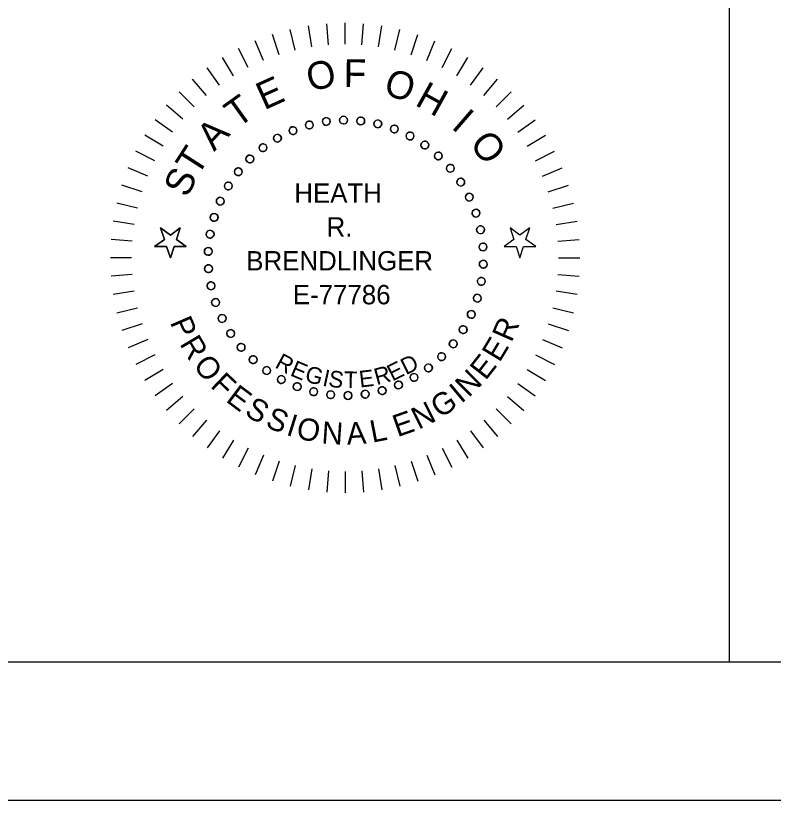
# Model space of a CAD drawing. Extents: x -5.9 to 34, y 0 to 22.
# Drawn here: x 23.816 to 26.559, y 0 to 2.839 of the extents above; entities that cross this region are included whole.
import ezdxf

# ---------------------------------------------------------------- set-up
doc = ezdxf.new("R2010")
doc.units = 0
for name, color, linetype in [('Default', 7, 'Continuous'), ('SH_Border', 7, 'Continuous'), ('SH_Cut_Line', 7, 'Continuous'), ('SH_Data', 7, 'Continuous')]:
    doc.layers.add(name, color=color, linetype=linetype)

msp = doc.modelspace()

# ---------------------------------------------------------------- linework, layer by layer
at = {"layer": 'Default'}
for points in [[(25.009, 2.7357), (25.009, 2.8128)], [(24.8286, 2.7144), (24.8106, 2.7893)], [(24.8881, 2.7262), (24.8761, 2.8023)], [(24.9484, 2.7334), (24.9423, 2.8102)], [(25.0697, 2.7334), (25.0757, 2.8102)], [(25.1299, 2.7262), (25.142, 2.8023)], [(25.1895, 2.7144), (25.2075, 2.7893)], [(24.7702, 2.6979), (24.7464, 2.7712)], [(25.2479, 2.6979), (25.2717, 2.7712)], [(24.7132, 2.6769), (24.6837, 2.7481)], [(25.3048, 2.6769), (25.3343, 2.7481)], [(24.6581, 2.6515), (24.6231, 2.7202)], [(25.3599, 2.6515), (25.3949, 2.7202)], [(24.6052, 2.6218), (24.5649, 2.6876)], [(25.4129, 2.6218), (25.4532, 2.6876)], [(24.5547, 2.5881), (24.5094, 2.6505)], [(25.4634, 2.5881), (25.5087, 2.6505)], [(24.507, 2.5505), (24.457, 2.6092)], [(25.511, 2.5505), (25.5611, 2.6092)], [(24.4625, 2.5094), (24.408, 2.5638)], [(25.5556, 2.5094), (25.6101, 2.5638)], [(24.4213, 2.4648), (24.3627, 2.5148)], [(25.5968, 2.4648), (25.6554, 2.5148)], [(24.3837, 2.4171), (24.3213, 2.4624)], [(25.6344, 2.4171), (25.6967, 2.4624)], [(24.35, 2.3667), (24.2843, 2.4069)], [(25.6681, 2.3667), (25.7338, 2.4069)], [(24.3203, 2.3137), (24.2517, 2.3487)], [(25.6977, 2.3137), (25.7664, 2.3487)], [(24.2949, 2.2586), (24.2237, 2.2881)], [(25.7231, 2.2586), (25.7943, 2.2881)], [(24.2739, 2.2016), (24.2006, 2.2255)], [(25.7442, 2.2016), (25.8174, 2.2255)], [(24.2574, 2.1432), (24.1825, 2.1612)], [(25.7606, 2.1432), (25.8356, 2.1612)], [(24.2456, 2.0837), (24.1695, 2.0958)], [(25.7725, 2.0837), (25.8486, 2.0958)], [(24.3545, 2.0295), (24.3192, 2.0039), (24.3628, 2.0039), (24.3762, 1.9624), (24.3897, 2.0039), (24.4333, 2.0039), (24.398, 2.0295), (24.4115, 2.071), (24.3762, 2.0454), (24.341, 2.071), (24.3545, 2.0295)], [(25.6771, 2.071), (25.6418, 2.0454), (25.6065, 2.071), (25.62, 2.0295), (25.5847, 2.0039), (25.6283, 2.0039), (25.6418, 1.9624), (25.6553, 2.0039), (25.6989, 2.0039), (25.6636, 2.0295), (25.6771, 2.071)], [(24.2385, 2.0234), (24.1616, 2.0295)], [(25.7796, 2.0234), (25.8564, 2.0295)], [(24.2361, 1.9628), (24.159, 1.9628)], [(25.782, 1.9628), (25.8591, 1.9628)], [(24.2385, 1.9021), (24.1616, 1.8961)], [(25.7796, 1.9021), (25.8564, 1.8961)], [(24.2456, 1.8419), (24.1695, 1.8298)], [(25.8486, 1.8298), (25.7725, 1.8419)], [(24.1825, 1.7644), (24.2574, 1.7823)], [(25.7606, 1.7823), (25.8356, 1.7644)], [(24.2739, 1.7239), (24.2006, 1.7001)], [(25.7442, 1.7239), (25.8174, 1.7001)], [(24.2949, 1.667), (24.2237, 1.6375)], [(25.7231, 1.667), (25.7943, 1.6375)], [(24.3203, 1.6119), (24.2517, 1.5769)], [(25.6977, 1.6119), (25.7664, 1.5769)], [(24.35, 1.5589), (24.2843, 1.5187)], [(25.6681, 1.5589), (25.7338, 1.5187)], [(24.3837, 1.5085), (24.3213, 1.4632)], [(25.6344, 1.5085), (25.6967, 1.4632)], [(24.4213, 1.4608), (24.3627, 1.4107)], [(25.5968, 1.4608), (25.6554, 1.4107)], [(24.4625, 1.4162), (24.408, 1.3617)], [(25.5556, 1.4162), (25.6101, 1.3617)], [(24.507, 1.375), (24.457, 1.3164)], [(25.511, 1.375), (25.5611, 1.3164)], [(24.5547, 1.3375), (24.5094, 1.2751)], [(25.4634, 1.3375), (25.5087, 1.2751)], [(24.6052, 1.3037), (24.5649, 1.238)], [(25.4129, 1.3037), (25.4532, 1.238)], [(24.6581, 1.2741), (24.6231, 1.2054)], [(25.3599, 1.2741), (25.3949, 1.2054)], [(24.7132, 1.2487), (24.6837, 1.1775)], [(24.7702, 1.2277), (24.7464, 1.1544)], [(25.2479, 1.2277), (25.2717, 1.1544)], [(25.3048, 1.2487), (25.3343, 1.1775)], [(24.8286, 1.2112), (24.8106, 1.1363)], [(24.8881, 1.1993), (24.8761, 1.1232)], [(25.1299, 1.1993), (25.142, 1.1232)], [(25.1895, 1.2112), (25.2075, 1.1363)], [(24.9484, 1.1922), (24.9423, 1.1154)], [(25.009, 1.1898), (25.009, 1.1128)], [(25.0697, 1.1922), (25.0757, 1.1154)]]:
    msp.add_lwpolyline(points, dxfattribs=at)
for points in [[(24.341, 2.071), (24.3762, 2.0454), (24.4115, 2.071), (24.398, 2.0295), (24.4333, 2.0039), (24.3897, 2.0039), (24.3762, 1.9624), (24.3628, 2.0039), (24.3192, 2.0039), (24.3545, 2.0295)], [(25.6771, 2.071), (25.6418, 2.0454), (25.6065, 2.071), (25.62, 2.0295), (25.5847, 2.0039), (25.6283, 2.0039), (25.6418, 1.9624), (25.6553, 2.0039), (25.6989, 2.0039), (25.6636, 2.0295)]]:
    msp.add_lwpolyline(points, close=True, dxfattribs=at)
for centre in [(24.9407, 2.4564), (25.0031, 2.4613), (25.0656, 2.4584), (24.8794, 2.4437), (25.1273, 2.4477), (25.1871, 2.4293), (24.8202, 2.4234), (25.2441, 2.4036), (24.764, 2.3958), (25.2975, 2.3709), (24.7118, 2.3614), (24.6642, 2.3207), (25.3464, 2.3318), (25.39, 2.2869), (24.6221, 2.2744), (25.4276, 2.2369), (24.5861, 2.2232), (25.4586, 2.1826), (24.5569, 2.1679), (25.4826, 2.1247), (24.5348, 2.1093), (25.4991, 2.0644), (24.5202, 2.0485), (25.508, 2.0024), (24.5134, 1.9863), (24.5144, 1.9237), (25.509, 1.9399), (24.5233, 1.8617), (25.5022, 1.8777), (25.4876, 1.8168), (24.5398, 1.8014), (25.4655, 1.7582), (24.5638, 1.7436), (25.4362, 1.7029), (24.5948, 1.6892), (24.6324, 1.6392), (25.4003, 1.6517), (25.3582, 1.6054), (24.676, 1.5943), (24.7249, 1.5552), (25.3106, 1.5647), (24.7783, 1.5225), (25.2583, 1.5303), (24.8353, 1.4968), (25.2022, 1.5028), (24.8951, 1.4784), (24.9568, 1.4677), (25.0193, 1.4648), (25.0817, 1.4697), (25.143, 1.4825)]:
    msp.add_circle(centre, 0.0141, dxfattribs=at)
for centre, radius, start, end in [((24.9407, 2.4564), 0.0141, 7.2, 187.2), ((25.0031, 2.4613), 0.0141, 0, 180), ((25.0656, 2.4584), 0.0141, 352.8, 172.8), ((24.8794, 2.4437), 0.0141, 14.4, 194.4), ((24.8794, 2.4437), 0.0141, 292.5271, 14.4), ((24.9407, 2.4564), 0.0141, 187.2, 270.9371), ((25.0112, 1.9631), 0.4843, 97.9226, 98.3416), ((24.9407, 2.4564), 0.0141, 285.3271, 7.2), ((25.0031, 2.4613), 0.0141, 180, 263.7371), ((25.0112, 1.9631), 0.4843, 90.7226, 91.1416), ((25.0031, 2.4613), 0.0141, 278.1271, 360), ((25.0656, 2.4584), 0.0141, 172.8, 256.5371), ((25.0112, 1.9631), 0.4843, 83.5226, 83.9416), ((25.0656, 2.4584), 0.0141, 270.9271, 352.8), ((25.1273, 2.4477), 0.0141, 165.6, 249.3371), ((25.1273, 2.4477), 0.0141, 345.6, 165.6), ((25.1273, 2.4477), 0.0141, 263.7271, 345.6), ((25.1871, 2.4293), 0.0141, 338.4, 158.4), ((24.8202, 2.4234), 0.0141, 21.6, 201.6), ((24.8202, 2.4234), 0.0141, 201.6, 285.3371), ((24.8202, 2.4234), 0.0141, 299.7271, 21.6), ((24.8794, 2.4437), 0.0141, 194.4, 278.1371), ((25.0112, 1.9631), 0.4843, 105.1226, 105.5416), ((25.0112, 1.9631), 0.4843, 76.3226, 76.7416), ((25.1871, 2.4293), 0.0141, 158.4, 242.1371), ((25.0112, 1.9631), 0.4843, 69.1226, 69.5416), ((25.1871, 2.4293), 0.0141, 256.5271, 338.4), ((25.2441, 2.4036), 0.0141, 331.2, 151.2), ((24.764, 2.3958), 0.0141, 28.8, 208.8), ((24.764, 2.3958), 0.0141, 208.8, 292.5371), ((24.764, 2.3958), 0.0141, 306.9271, 28.8), ((25.0112, 1.9631), 0.4843, 112.3226, 112.7416), ((25.2441, 2.4036), 0.0141, 151.2, 234.9371), ((25.0112, 1.9631), 0.4843, 61.9226, 62.3416), ((25.2441, 2.4036), 0.0141, 249.3271, 331.2), ((25.2975, 2.3709), 0.0141, 324, 144), ((24.7118, 2.3614), 0.0141, 36, 216), ((24.7118, 2.3614), 0.0141, 314.1271, 36), ((25.0112, 1.9631), 0.4843, 119.5226, 119.9416), ((25.2975, 2.3709), 0.0141, 144, 227.7371), ((25.0112, 1.9631), 0.4843, 54.7226, 55.1416), ((25.2975, 2.3709), 0.0141, 242.1271, 324), ((24.6642, 2.3207), 0.0141, 43.2, 223.2), ((24.6642, 2.3207), 0.0141, 321.3271, 43.2), ((24.7118, 2.3614), 0.0141, 216, 299.7371), ((25.0112, 1.9631), 0.4843, 126.7226, 127.1416), ((25.3464, 2.3318), 0.0141, 136.8, 220.5371), ((25.3464, 2.3318), 0.0141, 316.8, 136.8), ((24.6642, 2.3207), 0.0141, 223.2, 306.9371), ((25.0112, 1.9631), 0.4843, 133.9226, 134.3416), ((25.0112, 1.9631), 0.4843, 47.5226, 47.9416), ((25.3464, 2.3318), 0.0141, 234.9271, 316.8), ((25.39, 2.2869), 0.0141, 309.6, 129.6), ((24.6221, 2.2744), 0.0141, 50.4, 230.4), ((24.6221, 2.2744), 0.0141, 328.5271, 50.4), ((25.39, 2.2869), 0.0141, 129.6, 213.3371), ((25.0112, 1.9631), 0.4843, 40.3226, 40.7416), ((25.39, 2.2869), 0.0141, 227.7271, 309.6), ((24.6221, 2.2744), 0.0141, 230.4, 314.1371), ((25.0112, 1.9631), 0.4843, 141.1226, 141.5416), ((25.4276, 2.2369), 0.0141, 122.4, 206.1371), ((25.4276, 2.2369), 0.0141, 302.4, 122.4), ((24.5861, 2.2232), 0.0141, 57.6, 237.6), ((24.5861, 2.2232), 0.0141, 335.7271, 57.6), ((25.0112, 1.9631), 0.4843, 148.3226, 148.7416), ((25.0112, 1.9631), 0.4843, 33.1226, 33.5416), ((25.4276, 2.2369), 0.0141, 220.5271, 302.4), ((24.5861, 2.2232), 0.0141, 237.6, 321.3371), ((25.4586, 2.1826), 0.0141, 115.2, 198.9371), ((25.4586, 2.1826), 0.0141, 295.2, 115.2), ((24.5569, 2.1679), 0.0141, 64.8, 244.8), ((24.5569, 2.1679), 0.0141, 244.8, 328.5371), ((24.5569, 2.1679), 0.0141, 342.9271, 64.8), ((25.0112, 1.9631), 0.4843, 155.5226, 155.9416), ((25.0112, 1.9631), 0.4843, 25.9226, 26.3416), ((25.4586, 2.1826), 0.0141, 213.3271, 295.2), ((25.4826, 2.1247), 0.0141, 108, 191.7371), ((25.4826, 2.1247), 0.0141, 288, 108), ((24.5348, 2.1093), 0.0141, 72, 252), ((24.5348, 2.1093), 0.0141, 252, 335.7371), ((24.5348, 2.1093), 0.0141, 350.1271, 72), ((25.0112, 1.9631), 0.4843, 162.7226, 163.1416), ((25.0112, 1.9631), 0.4843, 18.7226, 19.1416), ((25.4826, 2.1247), 0.0141, 206.1271, 288), ((25.4991, 2.0644), 0.0141, 100.8, 184.5371), ((25.4991, 2.0644), 0.0141, 280.8, 100.8), ((24.5202, 2.0485), 0.0141, 79.2, 259.2), ((24.5202, 2.0485), 0.0141, 259.2, 342.9371), ((24.5202, 2.0485), 0.0141, 357.3271, 79.2), ((25.0112, 1.9631), 0.4843, 169.9226, 170.3416), ((25.0112, 1.9631), 0.4843, 11.5226, 11.9416), ((25.4991, 2.0644), 0.0141, 198.9271, 280.8), ((25.508, 2.0024), 0.0141, 93.6, 177.3371), ((25.508, 2.0024), 0.0141, 273.6, 93.6), ((24.5134, 1.9863), 0.0141, 86.4, 266.4), ((24.5134, 1.9863), 0.0141, 4.5271, 86.4), ((25.0112, 1.9631), 0.4843, 4.3226, 4.7416), ((25.508, 2.0024), 0.0141, 191.7271, 273.6), ((24.5134, 1.9863), 0.0141, 266.4, 350.1371), ((25.0112, 1.9631), 0.4843, 177.1226, 177.5416), ((24.5144, 1.9237), 0.0141, 93.6, 273.6), ((24.5144, 1.9237), 0.0141, 11.7271, 93.6), ((25.0112, 1.9631), 0.4843, 357.1226, 357.5416), ((25.509, 1.9399), 0.0141, 184.5271, 266.4), ((25.509, 1.9399), 0.0141, 86.4, 170.1371), ((25.509, 1.9399), 0.0141, 266.4, 86.4), ((24.5144, 1.9237), 0.0141, 273.6, 357.3371), ((25.0112, 1.9631), 0.4843, 184.3226, 184.7416), ((24.5233, 1.8617), 0.0141, 100.8, 280.8), ((24.5233, 1.8617), 0.0141, 18.9271, 100.8), ((25.0112, 1.9631), 0.4843, 349.9226, 350.3416), ((25.5022, 1.8777), 0.0141, 177.3271, 259.2), ((25.5022, 1.8777), 0.0141, 79.2, 162.9371), ((25.5022, 1.8777), 0.0141, 259.2, 79.2), ((24.5233, 1.8617), 0.0141, 280.8, 4.5371), ((25.0112, 1.9631), 0.4843, 191.5226, 191.9416), ((25.4876, 1.8168), 0.0141, 170.1271, 252), ((25.0112, 1.9631), 0.4843, 342.7226, 343.1416), ((25.4876, 1.8168), 0.0141, 72, 155.7371), ((25.4876, 1.8168), 0.0141, 252, 72), ((24.5398, 1.8014), 0.0141, 108, 288), ((24.5398, 1.8014), 0.0141, 26.1271, 108), ((24.5398, 1.8014), 0.0141, 288, 11.7371), ((25.0112, 1.9631), 0.4843, 198.7226, 199.1416), ((25.4655, 1.7582), 0.0141, 162.9271, 244.8), ((25.0112, 1.9631), 0.4843, 335.5226, 335.9416), ((25.4655, 1.7582), 0.0141, 64.8, 148.5371), ((25.4655, 1.7582), 0.0141, 244.8, 64.8), ((24.5638, 1.7436), 0.0141, 115.2, 295.2), ((24.5638, 1.7436), 0.0141, 33.3271, 115.2), ((24.5638, 1.7436), 0.0141, 295.2, 18.9371), ((25.0112, 1.9631), 0.4843, 205.9226, 206.3416), ((25.4362, 1.7029), 0.0141, 155.7271, 237.6), ((25.0112, 1.9631), 0.4843, 328.3226, 328.7416), ((25.4362, 1.7029), 0.0141, 57.6, 141.3371), ((25.4362, 1.7029), 0.0141, 237.6, 57.6), ((24.5948, 1.6892), 0.0141, 122.4, 302.4), ((24.5948, 1.6892), 0.0141, 40.5271, 122.4), ((24.5948, 1.6892), 0.0141, 302.4, 26.1371), ((25.0112, 1.9631), 0.4843, 213.1226, 213.5416), ((24.6324, 1.6392), 0.0141, 129.6, 309.6), ((24.6324, 1.6392), 0.0141, 47.7271, 129.6), ((24.6324, 1.6392), 0.0141, 309.6, 33.3371), ((25.0112, 1.9631), 0.4843, 220.3226, 220.7416), ((25.4003, 1.6517), 0.0141, 148.5271, 230.4), ((25.0112, 1.9631), 0.4843, 321.1226, 321.5416), ((25.4003, 1.6517), 0.0141, 50.4, 134.1371), ((25.4003, 1.6517), 0.0141, 230.4, 50.4), ((25.3582, 1.6054), 0.0141, 43.2, 126.9371), ((24.676, 1.5943), 0.0141, 136.8, 316.8), ((24.676, 1.5943), 0.0141, 54.9271, 136.8), ((25.0112, 1.9631), 0.4843, 227.5226, 227.9416), ((24.676, 1.5943), 0.0141, 316.8, 40.5371), ((25.3582, 1.6054), 0.0141, 141.3271, 223.2), ((25.0112, 1.9631), 0.4843, 313.9226, 314.3416), ((25.3582, 1.6054), 0.0141, 223.2, 43.2), ((24.7249, 1.5552), 0.0141, 144, 324), ((24.7249, 1.5552), 0.0141, 62.1271, 144), ((25.0112, 1.9631), 0.4843, 234.7226, 235.1416), ((24.7249, 1.5552), 0.0141, 324, 47.7371), ((25.3106, 1.5647), 0.0141, 134.1271, 216), ((25.3106, 1.5647), 0.0141, 216, 36), ((25.0112, 1.9631), 0.4843, 306.7226, 307.1416), ((25.3106, 1.5647), 0.0141, 36, 119.7371), ((24.7783, 1.5225), 0.0141, 69.3271, 151.2), ((25.0112, 1.9631), 0.4843, 241.9226, 242.3416), ((24.7783, 1.5225), 0.0141, 331.2, 54.9371), ((25.2583, 1.5303), 0.0141, 126.9271, 208.8), ((25.2583, 1.5303), 0.0141, 208.8, 28.8), ((25.0112, 1.9631), 0.4843, 299.5226, 299.9416), ((25.2583, 1.5303), 0.0141, 28.8, 112.5371), ((24.7783, 1.5225), 0.0141, 151.2, 331.2), ((24.8353, 1.4968), 0.0141, 76.5271, 158.4), ((25.0112, 1.9631), 0.4843, 249.1226, 249.5416), ((24.8353, 1.4968), 0.0141, 338.4, 62.1371), ((25.2022, 1.5028), 0.0141, 119.7271, 201.6), ((25.2022, 1.5028), 0.0141, 201.6, 21.6), ((25.0112, 1.9631), 0.4843, 292.3226, 292.7416), ((25.2022, 1.5028), 0.0141, 21.6, 105.3371), ((24.8353, 1.4968), 0.0141, 158.4, 338.4), ((24.8951, 1.4784), 0.0141, 165.6, 345.6), ((24.8951, 1.4784), 0.0141, 83.7271, 165.6), ((25.0112, 1.9631), 0.4843, 256.3226, 256.7416), ((24.8951, 1.4784), 0.0141, 345.6, 69.3371), ((24.9568, 1.4677), 0.0141, 90.9271, 172.8), ((25.0112, 1.9631), 0.4843, 263.5226, 263.9416), ((24.9568, 1.4677), 0.0141, 352.8, 76.5371), ((25.0193, 1.4648), 0.0141, 98.1271, 180), ((25.0112, 1.9631), 0.4843, 270.7226, 271.1416), ((25.0193, 1.4648), 0.0141, 360, 83.7371), ((25.0817, 1.4697), 0.0141, 105.3271, 187.2), ((25.0112, 1.9631), 0.4843, 277.9226, 278.3416), ((25.0817, 1.4697), 0.0141, 7.2, 90.9371), ((25.143, 1.4825), 0.0141, 112.5271, 194.4), ((25.143, 1.4825), 0.0141, 194.4, 14.4), ((25.0112, 1.9631), 0.4843, 285.1226, 285.5416), ((25.143, 1.4825), 0.0141, 14.4, 98.1371), ((24.9568, 1.4677), 0.0141, 172.8, 352.8), ((25.0193, 1.4648), 0.0141, 180, 0), ((25.0817, 1.4697), 0.0141, 187.2, 7.2)]:
    msp.add_arc(centre, radius, start, end, dxfattribs=at)
at = {"layer": 'SH_Border'}
msp.add_lwpolyline([(1.5, 21.5), (33.5, 21.5), (33.5, 0.5), (1.5, 0.5)], close=True, dxfattribs=at)
at = {"layer": 'SH_Cut_Line'}
msp.add_lwpolyline([(0, 0), (34, 0), (34, 22), (0, 22)], close=True, dxfattribs=at)
at = {"layer": 'SH_Data'}
msp.add_line((26.4, 0.5), (26.4, 3.75), dxfattribs=at)

# ---------------------------------------------------------------- texts
at = {"layer": 'Default'}
for s, height, rotation, p in [('O', 0.1, 13.3854, (24.8823, 2.5639)), ('F', 0.1, 359.678, (25.0037, 2.5812)), ('O', 0.1, 342.0191, (25.1437, 2.5563)), ('E', 0.1, 24.2623, (24.716, 2.4964)), ('H', 0.1, 330.9889, (25.2583, 2.5174)), ('T', 0.1, 35.6514, (24.6195, 2.4305)), ('I', 0.1, 319.1518, (25.3904, 2.434)), ('A', 0.1, 46.5856, (24.535, 2.3455)), ('O', 0.1, 307.5099, (25.4565, 2.3748)), ('T', 0.1, 57.2766, (24.4742, 2.2543)), ('S', 0.1, 64.8956, (24.4385, 2.1774)), ('P', 0.08, 293.3065, (24.374, 1.7298)), ('R', 0.08, 66.294, (25.6112, 1.6543)), ('R', 0.08, 300.7913, (24.4082, 1.6517)), ('E', 0.08, 58.867, (25.5679, 1.5817)), ('O', 0.08, 308.9294, (24.4563, 1.5722)), ('R', 0.06, 331.5179, (24.7514, 1.5678)), ('E', 0.06, 337.0101, (24.8066, 1.5385)), ('E', 0.06, 26.5869, (25.18, 1.515)), ('D', 0.06, 26.8755, (25.2294, 1.5379)), ('E', 0.08, 51.8972, (25.5175, 1.5167)), ('G', 0.06, 344.9102, (24.8599, 1.5166)), ('R', 0.06, 15.2924, (25.1232, 1.5018)), ('F', 0.08, 316.3676, (24.5183, 1.4975)), ('I', 0.06, 347.8825, (24.9242, 1.501)), ('S', 0.06, 351.4682, (24.9458, 1.4978)), ('T', 0.06, 359.0333, (25.0044, 1.4922)), ('E', 0.06, 6.5708, (25.0629, 1.4936)), ('N', 0.08, 44.7866, (25.4562, 1.455)), ('I', 0.08, 39.7574, (25.429, 1.4337)), ('E', 0.08, 323.0948, (24.5737, 1.4451)), ('G', 0.08, 34.2643, (25.3534, 1.3802)), ('S', 0.08, 330.2332, (24.6414, 1.395)), ('N', 0.08, 26.5487, (25.2748, 1.3406)), ('S', 0.08, 337.5402, (24.7166, 1.3529)), ('I', 0.08, 342.597, (24.7922, 1.323)), ('E', 0.08, 19.438, (25.1986, 1.3135)), ('O', 0.08, 348.1963, (24.8283, 1.3106)), ('N', 0.08, 356.0181, (24.9219, 1.2918)), ('A', 0.08, 3.7707, (25.0163, 1.2864)), ('L', 0.08, 10.971, (25.1071, 1.2938))]:
    msp.add_text(s, height=height, rotation=rotation, dxfattribs=at).set_placement(p)
for s, height, p in [('HEATH ', 0.07, (24.825, 2.1623)), ('R. ', 0.07, (24.9419, 2.0398)), ('BRENDLINGER', 0.069998, (24.6511, 1.9173)), ('E-77786', 0.07, (24.8196, 1.7948))]:
    msp.add_text(s, height=height, dxfattribs=at).set_placement(p)

doc.saveas('drawing.dxf')
